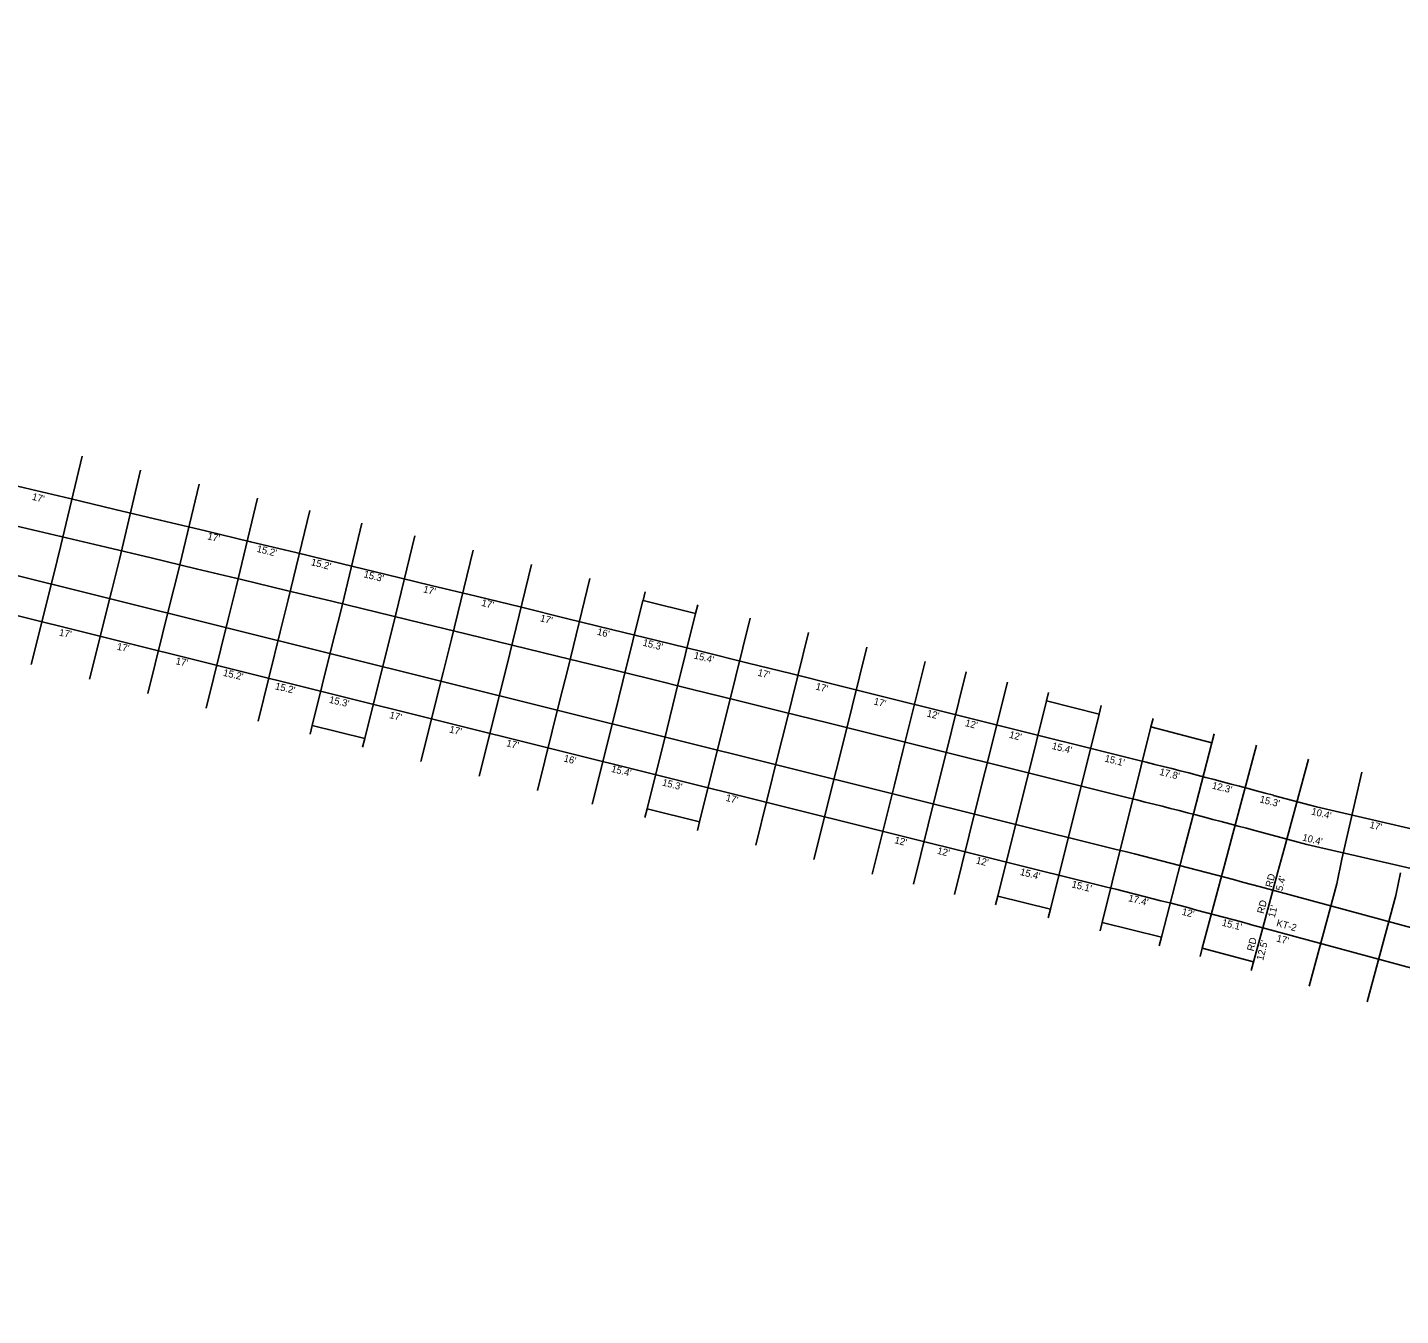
# Model space of a CAD drawing. Extents: x 4995357 to 4999033, y 3881202 to 3881750.
# Drawn here: x 4998265.1 to 4998653.9, y 3881294.1 to 3881658.9 of the extents above; entities that cross this region are included whole.
import ezdxf

# ---------------------------------------------------------------- set-up
doc = ezdxf.new("R2010")
doc.units = 0
for name, color, linetype in [('dsn3DCenterLine', 7, 'Continuous'), ('dsn3DCurbFormgrade', 7, 'Continuous'), ('dsn3DCurbTop', 7, 'Continuous'), ('dsn3DDitchFront', 7, 'Continuous'), ('dsn3DDNC', 7, 'Continuous'), ('dsn3DExistingPvmtBtm', 7, 'Continuous')]:
    doc.layers.add(name, color=color, linetype=linetype)

msp = doc.modelspace()

# ---------------------------------------------------------------- linework, layer by layer
at = {"layer": 'dsn3DCurbFormgrade'}
for p, q in [((4998272.48, 3881503.68), (4998266.19, 3881478.46)), ((4998288.97, 3881499.57), (4998282.69, 3881474.34)), ((4998305.47, 3881495.46), (4998299.18, 3881470.23)), ((4998321.96, 3881491.35), (4998315.68, 3881466.12)), ((4998336.69, 3881487.68), (4998330.41, 3881462.45)), ((4998351.42, 3881484.01), (4998345.74, 3881461.21)), ((4998366.3, 3881480.3), (4998360.62, 3881457.5)), ((4998502.79, 3881483.4), (4998496.51, 3881458.17)), ((4998382.8, 3881476.19), (4998376.51, 3881450.97)), ((4998519.29, 3881479.29), (4998513, 3881454.06)), ((4998399.29, 3881472.08), (4998393.01, 3881446.86)), ((4998553.63, 3881468.15), (4998547.95, 3881445.35)), ((4998415.79, 3881467.97), (4998409.5, 3881442.75)), ((4998568.54, 3881464.44), (4998562.86, 3881441.63)), ((4998431.31, 3881464.11), (4998425.03, 3881438.88)), ((4998446.22, 3881460.39), (4998440.54, 3881437.59)), ((4998583.23, 3881460.79), (4998577.53, 3881437.98)), ((4998461.1, 3881456.69), (4998455.41, 3881433.88)), ((4998477.59, 3881452.57), (4998471.31, 3881427.35)), ((4998600.51, 3881456.32), (4998594.63, 3881433.63)), ((4998606.41, 3881430.54), (4998613.08, 3881455.67)), ((4998627.88, 3881451.68), (4998621.06, 3881426.59)), ((4998494.09, 3881448.46), (4998487.8, 3881423.24)), ((4998642.98, 3881447.99), (4998637.31, 3881423.35)), ((4998510.58, 3881444.35), (4998504.3, 3881419.13)), ((4998545.52, 3881435.65), (4998539.85, 3881412.86)), ((4998560.43, 3881431.93), (4998554.76, 3881409.15)), ((4998575.11, 3881428.28), (4998569.4, 3881405.42)), ((4998592.39, 3881425), (4998586.23, 3881401.22)), ((4998604.31, 3881422.7), (4998597.75, 3881398.15)), ((4998619.2, 3881419.74), (4998614.91, 3881403.91)), ((4998635.91, 3881416.38), (4998628.04, 3881387.4)), ((4998652.61, 3881413.01), (4998644.44, 3881382.94))]:
    msp.add_line(p, q, dxfattribs=at)
at = {"layer": 'dsn3DCurbTop'}
for p, q in [((4998280.6, 3881537.48), (4998274.59, 3881512.18)), ((4998297.16, 3881533.54), (4998291.13, 3881508.25)), ((4998313.72, 3881529.59), (4998307.67, 3881504.3)), ((4998330.27, 3881525.62), (4998324.2, 3881500.34)), ((4998345.05, 3881522.07), (4998338.96, 3881496.79)), ((4998359.83, 3881518.5), (4998353.72, 3881493.23)), ((4998374.75, 3881514.89), (4998368.62, 3881489.62)), ((4998274.59, 3881512.18), (4998272.48, 3881503.68)), ((4998391.29, 3881510.87), (4998385.14, 3881485.61)), ((4998288.97, 3881499.57), (4998291.13, 3881508.25)), ((4998307.67, 3881504.3), (4998305.47, 3881495.46)), ((4998407.83, 3881506.84), (4998401.66, 3881481.58)), ((4998321.96, 3881491.35), (4998324.2, 3881500.34)), ((4998424.36, 3881502.79), (4998418.17, 3881477.54)), ((4998336.69, 3881487.68), (4998338.96, 3881496.79)), ((4998439.34, 3881496.63), (4998433.71, 3881473.72)), ((4998351.42, 3881484.01), (4998353.72, 3881493.23)), ((4998454.24, 3881492.92), (4998448.6, 3881470.06)), ((4998469.76, 3881491.61), (4998463.51, 3881466.37)), ((4998368.62, 3881489.62), (4998366.3, 3881480.3)), ((4998486.28, 3881487.51), (4998480.01, 3881462.28)), ((4998382.8, 3881476.19), (4998385.14, 3881485.61)), ((4998401.66, 3881481.58), (4998399.29, 3881472.08)), ((4998415.79, 3881467.97), (4998418.17, 3881477.54)), ((4998433.71, 3881473.72), (4998431.31, 3881464.11)), ((4998446.22, 3881460.39), (4998448.6, 3881470.06)), ((4998461.1, 3881456.69), (4998463.51, 3881466.37)), ((4998480.01, 3881462.28), (4998477.59, 3881452.57)), ((4998494.09, 3881448.46), (4998496.51, 3881458.17)), ((4998513, 3881454.06), (4998510.58, 3881444.35)), ((4998524.65, 3881451.15), (4998522.24, 3881441.45)), ((4998536.3, 3881448.25), (4998533.88, 3881438.55)), ((4998547.95, 3881445.35), (4998545.52, 3881435.65)), ((4998562.86, 3881441.63), (4998560.43, 3881431.93)), ((4998577.53, 3881437.98), (4998575.11, 3881428.28)), ((4998594.63, 3881433.63), (4998592.39, 3881425)), ((4998606.41, 3881430.54), (4998604.31, 3881422.7)), ((4998621.06, 3881426.59), (4998619.2, 3881419.74)), ((4998635.91, 3881416.38), (4998637.31, 3881423.35)), ((4998652.61, 3881413.01), (4998653.9, 3881419.44)), ((4998611.37, 3881404.87), (4998614.91, 3881403.91))]:
    msp.add_line(p, q, dxfattribs=at)
at = {"layer": 'dsn3DDitchFront'}
for q in [(4998611.63, 3881391.85), (4999019.28, 3881294.09)]:
    msp.add_line((4998614.91, 3881403.91), q, dxfattribs=at)
at = {"layer": 'dsn3DDNC'}
for p, q in [((4998247.68, 3881507.29), (4998573.41, 3881426.12)), ((4998245.02, 3881496.61), (4998570.75, 3881415.45)), ((4998494.37, 3881472.61), (4998579.48, 3881451.41)), ((4998491.71, 3881461.94), (4998576.82, 3881440.73)), ((4998617.94, 3881441.42), (4998630.07, 3881438.13)), ((4998630.07, 3881438.13), (4998703.22, 3881421.31)), ((4998615.06, 3881430.81), (4998627.39, 3881427.46)), ((4998627.39, 3881427.46), (4998700.75, 3881410.59)), ((4998614.25, 3881415.49), (4999021.9, 3881304.78))]:
    msp.add_line(p, q, dxfattribs=at)
for centre, radius, start, end in [((4993658.81, 3862065.98), 20000, 76.008501, 78.420039), ((4993658.81, 3862065.98), 19989, 76.008501, 78.420039), ((4998086.97, 3879474.84), 2037, 74.89079, 76.0085), ((4998086.97, 3879474.84), 2026, 74.89079, 76.0085), ((4998087.2, 3879474.79), 2011, 74.80613, 76.0085), ((4998087.2, 3879474.79), 2000, 74.80613, 76.0085)]:
    msp.add_arc(centre, radius, start, end, dxfattribs=at)
at = {"layer": 'dsn3DExistingPvmtBtm'}
for p, q in [((4998530.94, 3881476.38), (4998524.65, 3881451.15)), ((4998542.58, 3881473.48), (4998536.3, 3881448.25)), ((4998554.23, 3881470.58), (4998553.63, 3881468.15)), ((4998568.54, 3881464.44), (4998553.63, 3881468.15)), ((4998569.14, 3881466.86), (4998568.54, 3881464.44)), ((4998583.83, 3881463.2), (4998583.23, 3881460.79)), ((4998600.51, 3881456.32), (4998583.23, 3881460.79)), ((4998601.15, 3881458.8), (4998600.51, 3881456.32)), ((4998522.24, 3881441.45), (4998515.95, 3881416.22)), ((4998533.88, 3881438.55), (4998527.59, 3881413.32)), ((4998539.24, 3881410.42), (4998539.85, 3881412.86)), ((4998554.76, 3881409.15), (4998539.85, 3881412.86)), ((4998554.15, 3881406.7), (4998554.76, 3881409.15)), ((4998568.81, 3881403.05), (4998569.4, 3881405.42)), ((4998569.4, 3881405.42), (4998586.23, 3881401.22)), ((4998585.6, 3881398.78), (4998586.23, 3881401.22)), ((4998597.12, 3881395.76), (4998597.75, 3881398.15)), ((4998597.75, 3881398.15), (4998612.29, 3881394.27))]:
    msp.add_line(p, q, dxfattribs=at)
for points in [[(4998440.02, 3881499.04), (4998439.41, 3881496.61), (4998454.29, 3881492.91), (4998454.9, 3881495.33)], [(4998345.14, 3881458.78), (4998345.74, 3881461.21), (4998360.62, 3881457.5), (4998360.02, 3881455.08)], [(4998439.93, 3881435.16), (4998440.54, 3881437.59), (4998455.41, 3881433.88), (4998454.81, 3881431.46)]]:
    msp.add_lwpolyline(points, dxfattribs=at)

# ---------------------------------------------------------------- texts
at = {"layer": 'dsn3DCenterLine'}
for s, rotation, p in [("17'", 345.9626, (4998266.26, 3881525.15)), ("17'", 345.9626, (4998315.91, 3881513.96)), ("15.2'", 345.9626, (4998329.88, 3881510.41)), ("15.2'", 345.9626, (4998345.25, 3881506.63)), ("15.3'", 345.9626, (4998360.16, 3881503.2)), ("17'", 345.9626, (4998377.03, 3881498.95)), ("17'", 345.9626, (4998393.51, 3881495.12)), ("17'", 345.9626, (4998410.13, 3881490.75)), ("17'", 349.171, (4998273.96, 3881486.65)), ("16'", 345.9626, (4998426.26, 3881486.93)), ("17'", 349.171, (4998290.32, 3881482.66)), ("15.3'", 345.9626, (4998439.18, 3881483.83)), ("17'", 349.171, (4998306.97, 3881478.56)), ("15.4'", 345.9626, (4998453.65, 3881480.22)), ("15.2'", 347.114, (4998320.38, 3881475.29)), ("17'", 345.9626, (4998471.72, 3881475.33)), ("15.2'", 347.114, (4998335.1, 3881471.46)), ("17'", 345.9626, (4998488.12, 3881471.42)), ("15.3'", 347.114, (4998350.39, 3881467.65)), ("17'", 345.9626, (4998504.59, 3881467.2)), ("17'", 345.9626, (4998367.47, 3881463.32)), ("12'", 345.9626, (4998519.61, 3881463.78)), ("17'", 345.9626, (4998384.41, 3881459.26)), ("12'", 345.9626, (4998530.47, 3881461.07)), ("17'", 345.9626, (4998400.57, 3881455.35)), ("12'", 345.9626, (4998542.94, 3881457.76)), ("16'", 345.9626, (4998416.8, 3881451.04)), ("15.4'", 345.9626, (4998555.04, 3881454.59)), ("15.1'", 345.9626, (4998569.96, 3881451.03)), ("15.4'", 345.9626, (4998430.26, 3881448.09)), ("17.8'", 345.9626, (4998585.5, 3881447.24)), ("15.3'", 345.9626, (4998444.69, 3881444.22)), ("12.3'", 345.9626, (4998600.37, 3881443.37)), ("17'", 345.9626, (4998462.69, 3881439.89)), ("15.3'", 345.9626, (4998613.86, 3881439.46)), ("10.4'", 345.9626, (4998628.48, 3881436.03)), ("17'", 345.9626, (4998644.98, 3881432.24)), ("12'", 345.9626, (4998510.47, 3881427.91)), ("10.4'", 345.9626, (4998625.95, 3881428.66)), ("12'", 345.9626, (4998522.56, 3881424.89)), ("12'", 345.9626, (4998533.55, 3881422.15)), ("15.4'", 345.9626, (4998546.02, 3881418.9)), ('RD', 75.9626, (4998617.52, 3881415.2)), ("5.4'", 75.9626, (4998620.45, 3881414.19)), ("15.1'", 345.9626, (4998560.62, 3881415.39)), ("17.4'", 345.9626, (4998576.66, 3881411.47)), ('RD', 75.9626, (4998615.17, 3881407.74)), ("11'", 75.9626, (4998618.28, 3881406.62)), ("12'", 345.9626, (4998591.84, 3881407.62)), ("15.1'", 345.9626, (4998603.17, 3881404.52)), ('KT-2', 344.4604, (4998618.59, 3881404.42)), ('RD', 75.9626, (4998612.29, 3881397.15)), ("12.5'", 75.9626, (4998615, 3881394.51)), ("17'", 345.9626, (4998618.62, 3881400.06))]:
    msp.add_text(s, height=2, rotation=rotation, dxfattribs=at).set_placement(p)

doc.saveas('drawing.dxf')
